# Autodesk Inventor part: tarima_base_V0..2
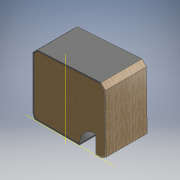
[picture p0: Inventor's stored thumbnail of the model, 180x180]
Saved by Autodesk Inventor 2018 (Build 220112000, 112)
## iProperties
Created: 2018-07
Part Number: tarima_base_V0..2
Material: Generic
Document SubType Name: Modeling
Designer: Gordillo
Density: 1 g/cm^3
Appearance: Default
Author: Gordillo
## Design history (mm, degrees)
sketch "Sketch1"
  geometry: L1 (2577.214, 0)-(-3201.591, 0) reference; L2 (0, -879.4)-(0, 4401.4) reference; L3 (-2041.67, 125)-(1673.33, 125); L4 (-2003.194, 3647)-(1533.653, 3456); L5 (1533.653, 3456)-(1751.67, 3249.921); L6 (1751.67, 335.921)-(1673.33, 125); L7 (-2003.194, 3647)-(-2208.33, 3435); L8 (1533.653, 3456)-(1751.67, 3249.921); L9 (1533.653, 3456)-(-2003.194, 3647); L10 (-2003.194, 3647)-(-2208.33, 3435); L11 (-2208.33, 3435)-(-2249.33, 249.263); L12 (-2041.67, 125)-(1673.33, 125); L13 (1673.33, 125)-(1751.67, 335.921); L14 (1751.67, 3249.921)-(1751.67, 335.921); L15 (-2041.67, 125)-(-1751.67, 125); L16 (-1751.67, 125)-(-817.67, 125); L17 (-1751.67, 125)-(-1751.67, 1059); L18 (1751.67, 335.921)-(1751.67, 3249.921); L19 (-2249.33, 249.263)-(-2041.67, 125); L20 (-353.67, 125)-(1093.33, 125); L21 (1093.33, 125)-(1093.33, -125); L22 (1093.33, -125)-(-353.67, -125); L23 (-353.67, -125)-(-353.67, 125); L24 (-2249.33, 249.263)-(-2208.33, 3435); L25 (-2376.048, 1860.393)-(-2376.016, 1862.892); A1 r 934 centre (-1751.67, 125) between (-817.67, 125) and (-1751.67, 1059); 1 further point
  constraints: 46 end point, 5 collinear, 3 parallel, 3 point on line, 2 point on circle, 2 vertical, 1 centre point, 1 horizontal, 1 perpendicular, 2 other
  dimensions: "d12" = 934 distance of L15.end L16.end; "d13" = 934 distance of L15.end L17.end; "d14" = 934 radius of A1; "d18" = 290 distance of L3.start A1.centre; "d19" = 4001 horizontal distance of L6.start L11.end; "largo_marco_ventana" = 1447 distance of L21.end L22.end; "ancho_ventana" = 250 distance of L20.end L21.end; "d22" = 464 distance from line of L16.end L23; "d23" = 580 distance of L3.end L20.end; "d24" = 242 distance of L3.start L11.end; "d25" = 225 distance of L6.start L3.end; "d26" = 2914 distance of L5.end L6.start; "d27" = 300 distance of L4.end L5.end; "d28" = 3542 distance of L4.start L4.end; "d29" = 295 distance of L4.start L7.end; "d30" = 3186 distance of L11.end L7.end; "d31" = 3522 vertical distance of L4.start L3.start; "d32" = 3331 vertical distance of L3.end L4.end; "d33" = 90 deg angle of L18 L12; "d34" = 3960 horizontal distance of L7.end L5.end
extrude "Extrusion2" new body sketch "Sketch1" distance "d16" = 20; taper "d17" = 0 deg
sketch "Sketch2"
  geometry: L1 (-1533.653, 3456)-(2003.194, 3647) reference; L2 (-1751.67, 3249.921)-(-1533.653, 3456) reference; L3 (-1751.67, 335.921)-(-1751.67, 3249.921) reference; L4 (-1673.33, 125)-(-1751.67, 335.921) reference; L5 (817.67, 125)-(-1673.33, 125) reference; L6 (1751.67, 125)-(1751.67, 1059) reference; L7 (2041.67, 125)-(1751.67, 125) reference; L8 (2249.33, 249.263)-(2041.67, 125) reference; L9 (2208.33, 3435)-(2249.33, 249.263) reference; L10 (2003.194, 3647)-(2208.33, 3435) reference; L11 (2329.916, 204.256)-(2063.778, 45); L12 (2063.778, 45)-(1751.67, 45); L13 (817.67, 45)-(-1728.956, 45); L14 (-1728.956, 45)-(-1831.67, 321.544); L15 (-1831.67, 321.544)-(-1831.67, 3284.385); L16 (-1831.67, 3284.385)-(-1567.276, 3534.301); L17 (-1567.276, 3534.301)-(2035.313, 3728.851); L18 (2035.313, 3728.851)-(2287.914, 3467.798); L19 (2287.914, 3467.798)-(2329.916, 204.256); L20 (817.67, 125)-(817.67, 45); L21 (1751.67, 125)-(1751.67, 1059) reference; L22 (1751.67, 125)-(1751.67, 45); L23 (2003.194, 3647)-(2035.313, 3728.851); L24 (817.67, 125)-(1751.67, 125); L25 (1751.67, 125)-(1751.67, 45); L26 (1751.67, 45)-(817.67, 45); L27 (817.67, 45)-(817.67, 125); A1 r 934 centre (1751.67, 125) between (1751.67, 1059) and (817.67, 125) reference; 1 further point
  constraints: 32 end point, 3 perpendicular, 2 parallel, 1 horizontal, 5 other
  dimensions: "d35" = 80 distance between parallel lines of L9 L19
extrude "Extrusion3" new body sketch "Sketch2" distance "d36" = 2334; taper "d37" = 0 deg
sketch "Sketch3"
  geometry: L1 (2208.33, 3435)-(2249.33, 249.263) reference; L2 (2287.914, 3467.798)-(2329.916, 204.256) reference; L3 (2035.313, 3728.851)-(2287.914, 3467.798) reference; L4 (2003.194, 3647)-(2208.33, 3435) reference; L5 (2003.194, 3647)-(2035.313, 3728.851) reference; L6 (2249.33, 249.263)-(2041.67, 125) reference; L7 (2329.916, 204.256)-(2063.778, 45) reference; L8 (2063.778, 45)-(1751.67, 45) reference; L9 (1751.67, 125)-(1751.67, 45) reference; L10 (2035.313, 3728.851)-(2003.194, 3647); L11 (2208.33, 3435)-(2003.194, 3647); L12 (2035.313, 3728.851)-(2287.914, 3467.798); L13 (2287.914, 3467.798)-(2329.916, 204.256); L14 (2329.916, 204.256)-(2063.778, 45); L15 (2063.778, 45)-(1751.67, 45); L16 (1751.67, 125)-(1751.67, 1059) reference; L17 (1751.67, 45)-(1751.67, 125); L18 (2249.33, 249.263)-(2041.67, 125) reference; L19 (1751.67, 125)-(2041.67, 125); L20 (2041.67, 125)-(2249.33, 249.263); L21 (2003.194, 3647)-(2208.33, 3435) reference; L22 (2249.33, 249.263)-(2208.33, 3435); L23 (-1533.653, 3456)-(2003.194, 3647) reference; L24 (2003.194, 3647)-(2035.313, 3728.851); L25 (2035.313, 3728.851)-(2287.914, 3467.798); L26 (2287.914, 3467.798)-(2329.916, 204.256); L27 (2329.916, 204.256)-(2063.778, 45); L28 (2063.778, 45)-(1751.67, 45); L29 (1751.67, 45)-(1751.67, 125); L30 (2041.67, 125)-(1751.67, 125) reference; L31 (1751.67, 125)-(2041.67, 125); L32 (2041.67, 125)-(2249.33, 249.263); L33 (2208.33, 3435)-(2249.33, 249.263) reference; L34 (2249.33, 249.263)-(2208.33, 3435); L35 (2208.33, 3435)-(2003.194, 3647); L36 (1751.67, 125)-(2041.67, 125); L37 (2041.67, 125)-(2041.67, 45); L38 (2041.67, 45)-(1751.67, 45); L39 (1751.67, 45)-(1751.67, 125); 1 further point
  constraints: 48 end point, 9 collinear, 6 parallel, 3 perpendicular, 1 horizontal, 1 point on line, 1 vertical
extrude "Extrusion4" new body sketch "Sketch3" distance "d38" = 2334; taper "d39" = 0 deg
sketch "Sketch4"
  geometry: L1 (580, 2061)-(2027, 2061); L2 (2027, 2061)-(2027, 1014); L3 (2027, 1014)-(580, 1014); L4 (580, 1014)-(580, 2061); L5 (580, 0)-(2027, 0) reference; L6 (2491, 0)-(3425, 0) reference; L7 (2491, 0)-(3425, 0) reference; L8 (2491, 0)-(3425, 0); L9 (3425, 0)-(3425, 2070); L10 (3425, 2070)-(2491, 2070); L11 (2491, 2070)-(2491, 0); 7 further points
  constraints: 16 end point, 4 parallel, 2 horizontal, 2 perpendicular, 2 point on line
  dimensions: "d40" = 1047 distance between parallel lines of L3 L1; "d41" = 1014 distance between parallel lines of L5 L3; "d42" = 2070 distance between parallel lines of L6 L10
extrude "Extrusion5" cut sketch "Sketch4" stored distance "d43" = 2334; taper "d44" = 0 deg
sketch "Sketch5"
  geometry: L1 (3715, -2334)-(0, -2334) reference; L2 (0, -2334)-(-78.34, -2334) reference; L3 (0, -2334)-(0, -64); L4 (0, -2334)-(2270, -2334); L5 (3737.108, -2334)-(3737.108, 0) reference; L6 (0, -64)-(3737.108, 0); 1 further point
  constraints: 6 end point, 1 horizontal, 1 perpendicular, 1 vertical
  dimensions: "d45" = 2270 distance of L1.end L3.end; "d46" = 90 deg angle of L4 L3 (derived)
workpoint "Work Point1"
workpoint "Work Point2"
workplane "Work Plane1"
split "Split1"
node "TarimaBase"
node "Projected Loop1"
node "paredes_front_lateral"
node "pared_trasera"
